// Mitsubishi GX Works2 project: 实例训练(搬运：步进指令)   PLC: FX3U/FX3UC

PROGRAM MAIN
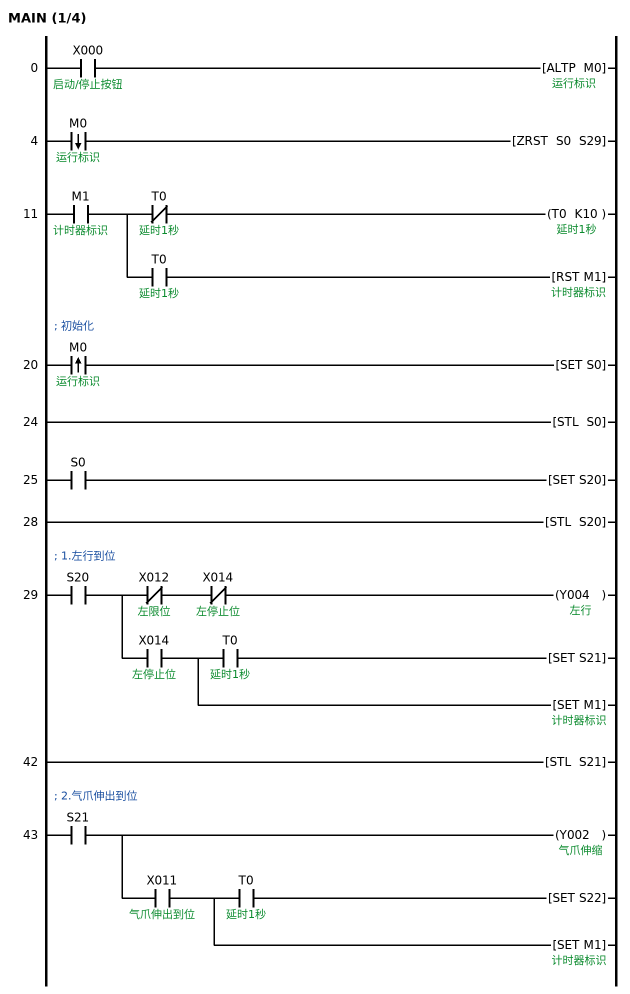
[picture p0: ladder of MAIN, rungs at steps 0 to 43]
0     LD      X000  ; 启动/停止按钮
      ALTP    M0  ; 运行标识
4     LDF     M0  ; 运行标识
      ZRST    S0 S29
        [note] 停止运行
11    LD      M1  ; 计时器标识
      MPS
      ANI     T0  ; 延时1秒
      OUT     T0 K10  ; 延时1秒
      MPP
      AND     T0  ; 延时1秒
      RST     M1  ; 计时器标识
; 初始化
20    LDP     M0  ; 运行标识
      SET     S0
24    STL     S0
25    LD      S0
      SET     S20
28    STL     S20
; 1.左行到位
29    LD      S20
      MPS
      ANI     X012  ; 左限位
      ANI     X014  ; 左停止位
      OUT     Y004  ; 左行
      MPP
      AND     X014  ; 左停止位
      MPS
      AND     T0  ; 延时1秒
      SET     S21
      MPP
      SET     M1  ; 计时器标识
42    STL     S21
; 2.气爪伸出到位
43    LD      S21
      OUT     Y002  ; 气爪伸缩
      AND     X011  ; 气爪伸出到位
      MPS
      AND     T0  ; 延时1秒
      SET     S22
      MPP
      SET     M1  ; 计时器标识
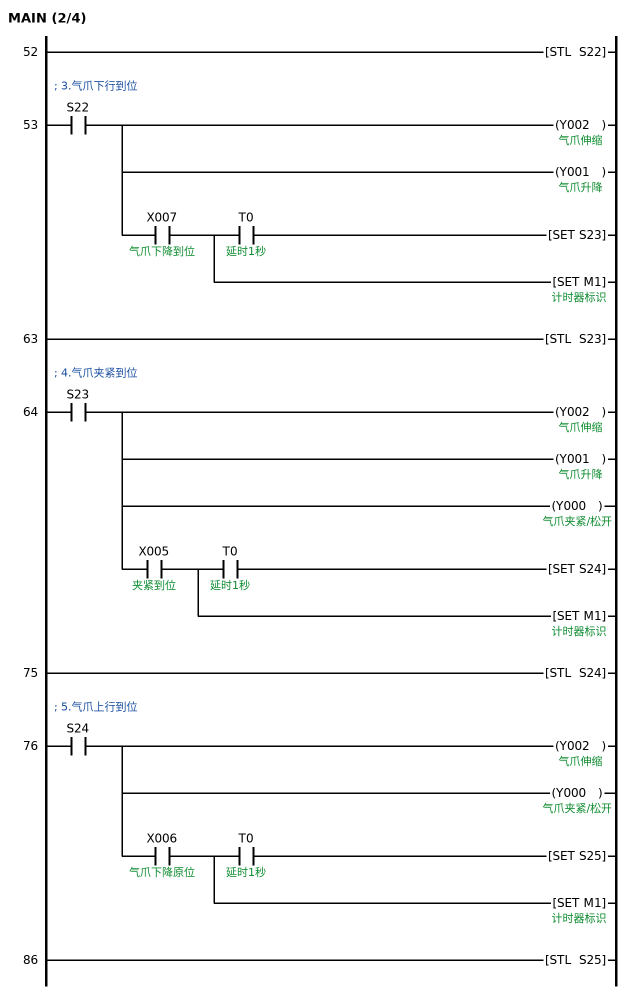
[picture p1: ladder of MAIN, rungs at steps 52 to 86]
52    STL     S22
; 3.气爪下行到位
53    LD      S22
      OUT     Y002  ; 气爪伸缩
      OUT     Y001  ; 气爪升降
      AND     X007  ; 气爪下降到位
      MPS
      AND     T0  ; 延时1秒
      SET     S23
      MPP
      SET     M1  ; 计时器标识
63    STL     S23
; 4.气爪夹紧到位
64    LD      S23
      OUT     Y002  ; 气爪伸缩
      OUT     Y001  ; 气爪升降
      OUT     Y000  ; 气爪夹紧/松开
      AND     X005  ; 夹紧到位
      MPS
      AND     T0  ; 延时1秒
      SET     S24
      MPP
      SET     M1  ; 计时器标识
75    STL     S24
; 5.气爪上行到位
76    LD      S24
      OUT     Y002  ; 气爪伸缩
      OUT     Y000  ; 气爪夹紧/松开
      AND     X006  ; 气爪下降原位
      MPS
      AND     T0  ; 延时1秒
      SET     S25
      MPP
      SET     M1  ; 计时器标识
86    STL     S25
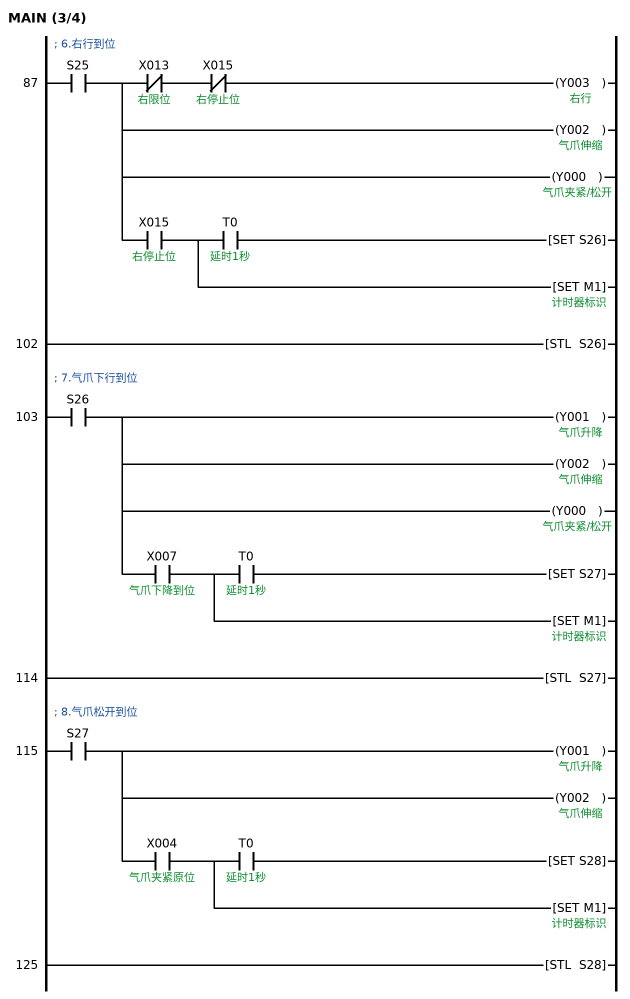
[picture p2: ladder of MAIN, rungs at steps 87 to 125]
; 6.右行到位
87    LD      S25
      MPS
      ANI     X013  ; 右限位
      ANI     X015  ; 右停止位
      OUT     Y003  ; 右行
      MPP
      OUT     Y002  ; 气爪伸缩
      OUT     Y000  ; 气爪夹紧/松开
      AND     X015  ; 右停止位
      MPS
      AND     T0  ; 延时1秒
      SET     S26
      MPP
      SET     M1  ; 计时器标识
102   STL     S26
; 7.气爪下行到位
103   LD      S26
      OUT     Y001  ; 气爪升降
      OUT     Y002  ; 气爪伸缩
      OUT     Y000  ; 气爪夹紧/松开
      AND     X007  ; 气爪下降到位
      MPS
      AND     T0  ; 延时1秒
      SET     S27
      MPP
      SET     M1  ; 计时器标识
114   STL     S27
; 8.气爪松开到位
115   LD      S27
      OUT     Y001  ; 气爪升降
      OUT     Y002  ; 气爪伸缩
      AND     X004  ; 气爪夹紧原位
      MPS
      AND     T0  ; 延时1秒
      SET     S28
      MPP
      SET     M1  ; 计时器标识
125   STL     S28
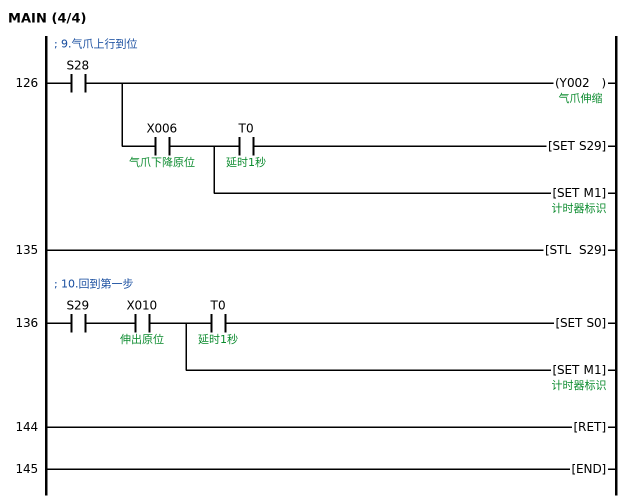
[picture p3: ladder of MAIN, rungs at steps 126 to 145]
; 9.气爪上行到位
126   LD      S28
      OUT     Y002  ; 气爪伸缩
      AND     X006  ; 气爪下降原位
      MPS
      AND     T0  ; 延时1秒
      SET     S29
      MPP
      SET     M1  ; 计时器标识
135   STL     S29
; 10.回到第一步
136   LD      S29
      AND     X010  ; 伸出原位
      MPS
      AND     T0  ; 延时1秒
      SET     S0
      MPP
      SET     M1  ; 计时器标识
144   RET
145   END
END_PROGRAM
